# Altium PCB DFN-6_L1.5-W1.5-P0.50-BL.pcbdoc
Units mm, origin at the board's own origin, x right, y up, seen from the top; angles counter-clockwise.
Board outline 14.45 x 15.06 mm, 2 copper layers (Top Layer, Bottom Layer), stack 0 mm thick; 1 components, 0 nets, 6 pads, 0 vias.
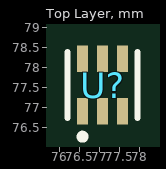
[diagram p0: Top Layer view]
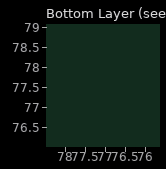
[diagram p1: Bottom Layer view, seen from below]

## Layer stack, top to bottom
Top Layer: signal copper (thickness not stored)
Bottom Layer: signal copper (thickness not stored)

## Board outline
84.302,69.85 69.85,69.85 69.85,84.905 84.302,84.905

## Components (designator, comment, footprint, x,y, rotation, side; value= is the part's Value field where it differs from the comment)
U? "" DFN-6_L1.5-W1.5-P0.50-BL 77.076,77.565 r0 top

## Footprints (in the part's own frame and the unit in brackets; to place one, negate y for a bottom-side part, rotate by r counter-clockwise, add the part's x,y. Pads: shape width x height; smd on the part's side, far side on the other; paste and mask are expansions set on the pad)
DFN-6_L1.5-W1.5-P0.50-BL [mm]
  rect 0.28x0.665 smd: 1(-0.5,-0.658) 2(0,-0.658) 3(0.5,-0.658) 4(0.5,0.658) 5(0,0.658) 6(-0.5,0.658)
  silkscreen extent -0.88,-1.36 0.88,0.83

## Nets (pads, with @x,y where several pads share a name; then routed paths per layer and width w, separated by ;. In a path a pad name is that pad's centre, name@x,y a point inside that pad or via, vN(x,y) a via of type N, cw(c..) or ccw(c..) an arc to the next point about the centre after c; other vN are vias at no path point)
pads on no net: U?.1 U?.2 U?.3 U?.4 U?.5 U?.6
